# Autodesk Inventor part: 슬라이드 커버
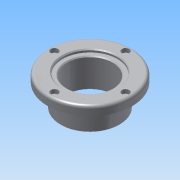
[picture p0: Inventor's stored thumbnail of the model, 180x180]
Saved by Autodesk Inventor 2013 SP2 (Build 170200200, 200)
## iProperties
Created: 2013-06
Part Number: 슬라이드 커버
Document SubType Name: Modeling
Designer: SeoGD™[esajin.kr]
Density: 2.71 g/cm^3
Material: 알루미늄 6061
Mass: 205.887 g
Surface Area: 227.998 cm^2
Volume: 75.9731 cm^3
Author: SeoGD™[esajin.kr]
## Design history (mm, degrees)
sketch "스케치1"
  geometry: C1 r 46 at (0, -39.25) reference; C2 r 32.5 at (0, -39.25) reference; 1 further point
  node "참조1"
  node "참조2"
extrude "돌출1" new body sketch "스케치1" distance "d0" = 10; taper "d1" = 0 deg
extrude "돌출2" join sketch "스케치1" distance "d2" = 25; taper "d3" = 0 deg
hole "구멍1" diameter "d6" = 50; stored, may be unused: countersink angle "d10" = 90 deg, drill point angle "d12" = 118 deg; dims "d4" = 10, "d5" = 10, "d7" = 6, "d8" = 4, "d9" = 2, "d11" = 8
sketch "스케치2"
  geometry: C1 r 46 at (0, 0) reference; C2 r 1.621 at (0, 39) reference; C3 r 1.621 at (39, 0) reference; C4 r 1.621 at (0, -39) reference; C5 r 1.621 at (-39, 0) reference; C6 r 33.5 at (0, 0) reference; 1 further point
hole "구멍2" sketch "스케치2" at (0, 39) diameter "d13" = 4.5; stored, may be unused: countersink angle "d17" = 90 deg, drill point angle "d19" = 118 deg; dims "d14" = 6, "d15" = 8, "d16" = 4.4, "d18" = 8
fillet "모깎기1" dims "d23" = 3
chamfer "모따기1" distance "d24" = 1; stored, may be unused: second distance "d25" = 2, angle "d26" = 45 deg
sketch "스케치3"
  geometry: C1 r 25 at (39, 0) reference; C2 r 30 at (39, 0); 1 further point
  constraints: 1 centre point, 1 coincident
  dimensions: "d27" = 60 diameter of C2
extrude "돌출3" cut sketch "스케치3" distance "d28" = 3; taper "d29" = 0 deg
chamfer "모따기2" distance "d30" = 1; stored, may be unused: second distance "d31" = 2, angle "d32" = 45 deg
node "솔리드1"
pattern_circular "원형 패턴1" dims angle "d21" = 360 deg
node "참조3"
